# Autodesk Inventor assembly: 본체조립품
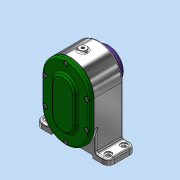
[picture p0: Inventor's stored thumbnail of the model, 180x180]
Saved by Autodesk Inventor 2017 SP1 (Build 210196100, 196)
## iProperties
Part Number: 본체조립품
Material: 일반
Document SubType Name: Assembly
Designer: MRC
Author: MRC
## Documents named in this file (19)
- C:\Users\MRC\Desktop\710609V1009\본체조립품.iam
- C:\Users\MRC\Desktop\710609V1009\본체.ipt
- C:\Users\MRC\Desktop\710609V1009\개스킷 A.ipt
- C:\Users\MRC\Desktop\710609V1009\개스킷 B.ipt
- C:\Users\MRC\Desktop\710609V1009\베어링 6001.ipt
- 베어링 6001.ipt
- C:\Users\MRC\Desktop\710609V1009\베어링 6002.ipt
- 베어링 6002.ipt
- C:\Users\MRC\Desktop\710609V1009\볼트 M4.ipt
- C:\Users\MRC\Desktop\710609V1009\스퍼기어 A.ipt
- C:\Users\MRC\Desktop\710609V1009\스퍼기어 B.ipt
- C:\Users\MRC\Desktop\710609V1009\오일 실 12 22 7.ipt
- C:\Users\MRC\Desktop\710609V1009\축 A.ipt
- C:\Users\MRC\Desktop\710609V1009\축 B.ipt
- C:\Users\MRC\Desktop\710609V1009\칼라.ipt
- C:\Users\MRC\Desktop\710609V1009\커버 A.ipt
- C:\Users\MRC\Desktop\710609V1009\커버 B.ipt
- C:\Users\MRC\Desktop\710609V1009\키 4 x 4 x 12.ipt
- C:\Users\MRC\Desktop\710609V1009\키 5 x 5 x 12.ipt
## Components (2 placed, 2 different names)
1. 개스킷 A:1
2. 개스킷 B:1
